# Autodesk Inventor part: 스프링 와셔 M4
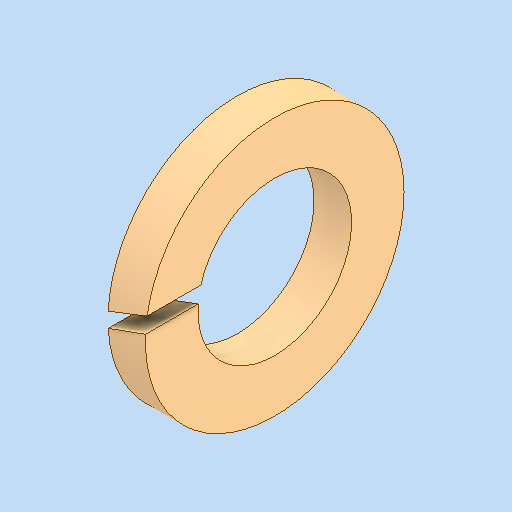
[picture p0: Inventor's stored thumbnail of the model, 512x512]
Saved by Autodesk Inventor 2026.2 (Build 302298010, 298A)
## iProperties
Created: 2026-03
Part Number: 스프링 와셔 M4
Material: 강철, 연강
Description: 스프링 잠금 와셔
Document SubType Name: Modeling
Designer: PC-2-06
Density: 7.85 g/cm^3
Appearance: 기본값
Author: jhkim
Sending System: Autodesk Inventor 2026
Preprocessor: ST-DEVELOPER v20.1
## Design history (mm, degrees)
feature "Solid1"
node "솔리드1"
